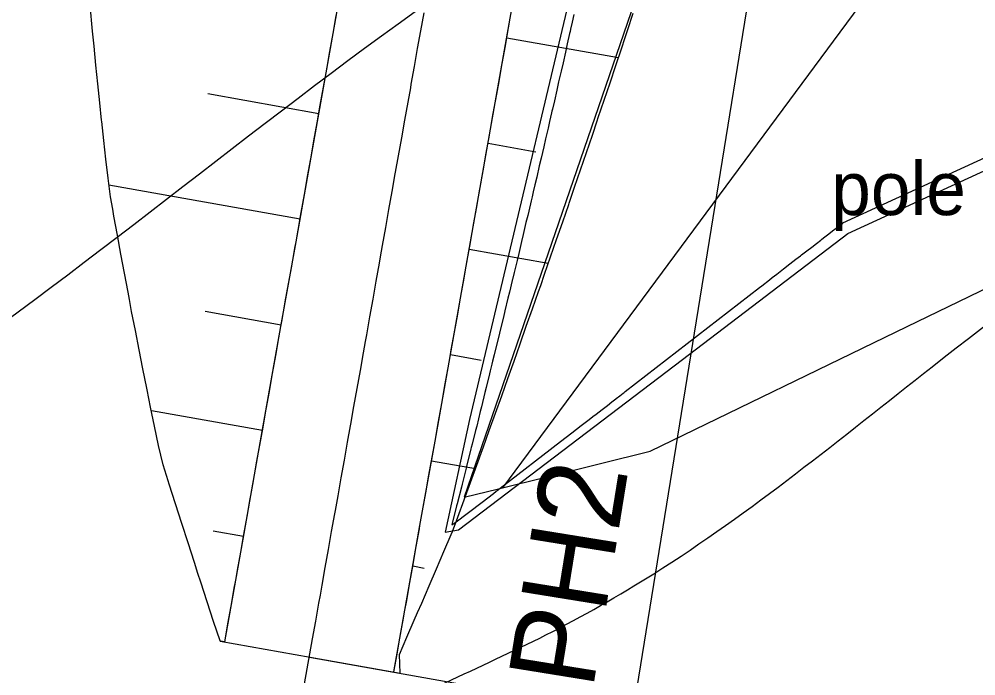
# Model space of a CAD drawing. Extents: x -564037 to -563827, y -1163561 to -1163412.
# Drawn here: x -563935.58 to -563924.45, y -1163502.82 to -1163495.18 of the extents above; entities that cross this region are included whole.
import ezdxf

# ---------------------------------------------------------------- set-up
doc = ezdxf.new("R2010")
doc.units = 0
for name, color, linetype in [('_popis staničení PH2', 7, 'Continuous'), ('_popis staničení T2', 7, 'Continuous'), ('Default', 7, 'Continuous'), ('Line', 7, 'Continuous'), ('Vrstva 24', 7, 'Continuous'), ('Vrstva 26', 7, 'Continuous'), ('Vrstva 40', 7, 'Continuous')]:
    doc.layers.add(name, color=color, linetype=linetype)

msp = doc.modelspace()

# ---------------------------------------------------------------- linework, layer by layer
msp.add_line((-563930.546, -1163501.066), (-563930.51, -1163501.042))
msp.add_lwpolyline([(-563930.469, -1163501.126), (-563927.863, -1163499.14), (-563925.937, -1163497.674), (-563921.059, -1163495.43), (-563912.613, -1163489.681), (-563911.421, -1163482.517), (-563913.266, -1163479.715), (-563914.137, -1163478.749), (-563916.309, -1163476.467), (-563917.281, -1163475.995), (-563923.761, -1163471.506), (-563924, -1163472.797), (-563925.435, -1163477.844), (-563927.008, -1163483.992), (-563927.659, -1163487.507), (-563928.13, -1163490.05), (-563928.806, -1163493.379), (-563930.34, -1163499.841), (-563930.622, -1163501.15)], close=True)
for points in [[(-563931.22, -1163502.778), (-563931.092, -1163502.06), (-563931.007, -1163501.582), (-563930.917, -1163501.075), (-563930.741, -1163500.09), (-563930.566, -1163499.106), (-563930.391, -1163498.121), (-563930.216, -1163497.137), (-563930.041, -1163496.152), (-563929.866, -1163495.168), (-563929.69, -1163494.183), (-563929.515, -1163493.199), (-563929.435, -1163492.745), (-563929.34, -1163492.214), (-563929.165, -1163491.23), (-563928.99, -1163490.245), (-563928.815, -1163489.261), (-563928.639, -1163488.276), (-563928.54, -1163487.717), (-563928.464, -1163487.297)], [(-563933.189, -1163502.428), (-563933.061, -1163501.709), (-563932.976, -1163501.232), (-563932.886, -1163500.725), (-563932.71, -1163499.74), (-563932.535, -1163498.756), (-563932.36, -1163497.771), (-563932.185, -1163496.786), (-563932.01, -1163495.802), (-563931.835, -1163494.817), (-563931.659, -1163493.833), (-563931.484, -1163492.848), (-563931.404, -1163492.395), (-563931.309, -1163491.864), (-563931.134, -1163490.879), (-563930.959, -1163489.895), (-563930.784, -1163488.91), (-563930.608, -1163487.926), (-563930.509, -1163487.367)], [(-563933.243, -1163502.42), (-563933.244, -1163502.418), (-563933.319, -1163502.19), (-563933.395, -1163501.962), (-563933.469, -1163501.733), (-563933.503, -1163501.631), (-563933.543, -1163501.505), (-563933.617, -1163501.277), (-563933.69, -1163501.049), (-563933.762, -1163500.822), (-563933.835, -1163500.594), (-563933.847, -1163500.554), (-563933.906, -1163500.366), (-563933.962, -1163500.141), (-563934.008, -1163499.918), (-563934.053, -1163499.695), (-563934.094, -1163499.494), (-563934.098, -1163499.473), (-563934.142, -1163499.25), (-563934.186, -1163499.027), (-563934.23, -1163498.804), (-563934.273, -1163498.582), (-563934.299, -1163498.442), (-563934.315, -1163498.359), (-563934.357, -1163498.137), (-563934.398, -1163497.915), (-563934.439, -1163497.693), (-563934.479, -1163497.471), (-563934.494, -1163497.391), (-563934.519, -1163497.249), (-563934.548, -1163497.029), (-563934.573, -1163496.809), (-563934.597, -1163496.59), (-563934.621, -1163496.371), (-563934.623, -1163496.353), (-563934.644, -1163496.152), (-563934.666, -1163495.933), (-563934.689, -1163495.714), (-563934.71, -1163495.495), (-563934.727, -1163495.318), (-563934.731, -1163495.277), (-563934.752, -1163495.058)], [(-563932.777, -1163505.821), (-563932.167, -1163502.395), (-563932.13, -1163502.186), (-563932.093, -1163501.978), (-563932.076, -1163501.884), (-563932.056, -1163501.77), (-563932.019, -1163501.562), (-563931.982, -1163501.353), (-563931.945, -1163501.145), (-563931.908, -1163500.937), (-563931.901, -1163500.9), (-563931.871, -1163500.728), (-563931.834, -1163500.52), (-563931.796, -1163500.312), (-563931.759, -1163500.103), (-563931.726, -1163499.915), (-563931.722, -1163499.895), (-563931.685, -1163499.687), (-563931.648, -1163499.479), (-563931.611, -1163499.27), (-563931.574, -1163499.062), (-563931.551, -1163498.931), (-563931.537, -1163498.854), (-563931.5, -1163498.645), (-563931.463, -1163498.437), (-563931.426, -1163498.229), (-563931.389, -1163498.02), (-563931.376, -1163497.946), (-563931.352, -1163497.812), (-563931.315, -1163497.604), (-563931.278, -1163497.396), (-563931.241, -1163497.187), (-563931.204, -1163496.979), (-563931.2, -1163496.962), (-563931.166, -1163496.771), (-563931.129, -1163496.562), (-563931.092, -1163496.354), (-563931.055, -1163496.146), (-563931.025, -1163495.977), (-563931.018, -1163495.937), (-563930.981, -1163495.729), (-563930.944, -1163495.521), (-563930.907, -1163495.313), (-563930.87, -1163495.104)], [(-563931.156, -1163502.575), (-563931.07, -1163502.375), (-563930.983, -1163502.176), (-563930.945, -1163502.086), (-563930.897, -1163501.976), (-563930.811, -1163501.776), (-563930.726, -1163501.577), (-563930.64, -1163501.377), (-563930.555, -1163501.177), (-563930.54, -1163501.142), (-563930.476, -1163500.976), (-563930.403, -1163500.775), (-563930.329, -1163500.573), (-563930.256, -1163500.371), (-563930.19, -1163500.188), (-563930.183, -1163500.169), (-563930.111, -1163499.967), (-563930.038, -1163499.765), (-563929.966, -1163499.563), (-563929.894, -1163499.361), (-563929.849, -1163499.234), (-563929.822, -1163499.159), (-563929.751, -1163498.957), (-563929.679, -1163498.754), (-563929.608, -1163498.552), (-563929.537, -1163498.35), (-563929.512, -1163498.278), (-563929.467, -1163498.148), (-563929.396, -1163497.945), (-563929.326, -1163497.743), (-563929.256, -1163497.54), (-563929.186, -1163497.338), (-563929.181, -1163497.321), (-563929.117, -1163497.135), (-563929.048, -1163496.933), (-563928.978, -1163496.73), (-563928.91, -1163496.528), (-563928.854, -1163496.363), (-563928.841, -1163496.325), (-563928.773, -1163496.122), (-563928.704, -1163495.919), (-563928.637, -1163495.717), (-563928.569, -1163495.514), (-563928.533, -1163495.405), (-563928.501, -1163495.311), (-563928.434, -1163495.108)], [(-563931.156, -1163502.575), (-563931.07, -1163502.375), (-563930.983, -1163502.176), (-563930.945, -1163502.086), (-563930.897, -1163501.976), (-563930.811, -1163501.776), (-563930.726, -1163501.577), (-563930.64, -1163501.377), (-563930.555, -1163501.177), (-563930.54, -1163501.142), (-563930.476, -1163500.976), (-563930.403, -1163500.775), (-563930.329, -1163500.573), (-563930.256, -1163500.371), (-563930.19, -1163500.188), (-563930.183, -1163500.169), (-563930.111, -1163499.967), (-563930.038, -1163499.765), (-563929.966, -1163499.563), (-563929.894, -1163499.361), (-563929.849, -1163499.234), (-563929.822, -1163499.159), (-563929.751, -1163498.957), (-563929.679, -1163498.754), (-563929.608, -1163498.552), (-563929.537, -1163498.35), (-563929.512, -1163498.278), (-563929.467, -1163498.148), (-563929.396, -1163497.945), (-563929.326, -1163497.743), (-563929.256, -1163497.54), (-563929.186, -1163497.338), (-563929.181, -1163497.321), (-563929.117, -1163497.135), (-563929.048, -1163496.933), (-563928.978, -1163496.73), (-563928.91, -1163496.528), (-563928.854, -1163496.363), (-563928.841, -1163496.325), (-563928.773, -1163496.122), (-563928.704, -1163495.919), (-563928.637, -1163495.717), (-563928.569, -1163495.514), (-563928.533, -1163495.405), (-563928.501, -1163495.311), (-563928.434, -1163495.108)], [(-563933.189, -1163502.43), (-563933.189, -1163502.428), (-563933.152, -1163502.22), (-563933.115, -1163502.011), (-563933.078, -1163501.803), (-563933.061, -1163501.709), (-563933.04, -1163501.595), (-563933.003, -1163501.386), (-563932.966, -1163501.178), (-563932.929, -1163500.97), (-563932.892, -1163500.762), (-563932.886, -1163500.725), (-563932.855, -1163500.553), (-563932.818, -1163500.345), (-563932.781, -1163500.137), (-563932.744, -1163499.928), (-563932.71, -1163499.74), (-563932.707, -1163499.72), (-563932.67, -1163499.512), (-563932.633, -1163499.303), (-563932.596, -1163499.095), (-563932.559, -1163498.887), (-563932.535, -1163498.756), (-563932.522, -1163498.679), (-563932.485, -1163498.47), (-563932.447, -1163498.262), (-563932.41, -1163498.054), (-563932.373, -1163497.845), (-563932.36, -1163497.771), (-563932.336, -1163497.637), (-563932.299, -1163497.429), (-563932.262, -1163497.22), (-563932.225, -1163497.012), (-563932.188, -1163496.804), (-563932.185, -1163496.786), (-563932.151, -1163496.596), (-563932.114, -1163496.387), (-563932.077, -1163496.179), (-563932.04, -1163495.971), (-563932.01, -1163495.802), (-563932.003, -1163495.762), (-563931.966, -1163495.554), (-563931.929, -1163495.346), (-563931.892, -1163495.137)], [(-563933.189, -1163502.43), (-563933.189, -1163502.428), (-563933.152, -1163502.22), (-563933.115, -1163502.011), (-563933.078, -1163501.803), (-563933.061, -1163501.709), (-563933.04, -1163501.595), (-563933.003, -1163501.386), (-563932.966, -1163501.178), (-563932.929, -1163500.97), (-563932.892, -1163500.762), (-563932.886, -1163500.725), (-563932.855, -1163500.553), (-563932.818, -1163500.345), (-563932.781, -1163500.137), (-563932.744, -1163499.928), (-563932.71, -1163499.74), (-563932.707, -1163499.72), (-563932.67, -1163499.512), (-563932.633, -1163499.303), (-563932.596, -1163499.095), (-563932.559, -1163498.887), (-563932.535, -1163498.756), (-563932.522, -1163498.679), (-563932.485, -1163498.47), (-563932.447, -1163498.262), (-563932.41, -1163498.054), (-563932.373, -1163497.845), (-563932.36, -1163497.771), (-563932.336, -1163497.637), (-563932.299, -1163497.429), (-563932.262, -1163497.22), (-563932.225, -1163497.012), (-563932.188, -1163496.804), (-563932.185, -1163496.786), (-563932.151, -1163496.596), (-563932.114, -1163496.387), (-563932.077, -1163496.179), (-563932.04, -1163495.971), (-563932.01, -1163495.802), (-563932.003, -1163495.762), (-563931.966, -1163495.554), (-563931.929, -1163495.346), (-563931.892, -1163495.137)], [(-563931.22, -1163502.78), (-563931.22, -1163502.778), (-563931.183, -1163502.57), (-563931.146, -1163502.362), (-563931.108, -1163502.153), (-563931.092, -1163502.06), (-563931.071, -1163501.945), (-563931.034, -1163501.737), (-563930.997, -1163501.528), (-563930.96, -1163501.32), (-563930.923, -1163501.112), (-563930.917, -1163501.075), (-563930.886, -1163500.904), (-563930.849, -1163500.695), (-563930.812, -1163500.487), (-563930.775, -1163500.279), (-563930.741, -1163500.09), (-563930.738, -1163500.07), (-563930.701, -1163499.862), (-563930.664, -1163499.654), (-563930.627, -1163499.445), (-563930.59, -1163499.237), (-563930.566, -1163499.106), (-563930.553, -1163499.029), (-563930.515, -1163498.821), (-563930.478, -1163498.612), (-563930.441, -1163498.404), (-563930.404, -1163498.196), (-563930.391, -1163498.121), (-563930.367, -1163497.987), (-563930.33, -1163497.779), (-563930.293, -1163497.571), (-563930.256, -1163497.362), (-563930.219, -1163497.154), (-563930.216, -1163497.137), (-563930.182, -1163496.946), (-563930.145, -1163496.738), (-563930.108, -1163496.529), (-563930.071, -1163496.321), (-563930.041, -1163496.152), (-563930.034, -1163496.113), (-563929.997, -1163495.904), (-563929.96, -1163495.696), (-563929.922, -1163495.488), (-563929.885, -1163495.279), (-563929.866, -1163495.168)], [(-563931.22, -1163502.78), (-563931.22, -1163502.778), (-563931.183, -1163502.57), (-563931.146, -1163502.362), (-563931.108, -1163502.153), (-563931.092, -1163502.06), (-563931.071, -1163501.945), (-563931.034, -1163501.737), (-563930.997, -1163501.528), (-563930.96, -1163501.32), (-563930.923, -1163501.112), (-563930.917, -1163501.075), (-563930.886, -1163500.904), (-563930.849, -1163500.695), (-563930.812, -1163500.487), (-563930.775, -1163500.279), (-563930.741, -1163500.09), (-563930.738, -1163500.07), (-563930.701, -1163499.862), (-563930.664, -1163499.654), (-563930.627, -1163499.445), (-563930.59, -1163499.237), (-563930.566, -1163499.106), (-563930.553, -1163499.029), (-563930.515, -1163498.821), (-563930.478, -1163498.612), (-563930.441, -1163498.404), (-563930.404, -1163498.196), (-563930.391, -1163498.121), (-563930.367, -1163497.987), (-563930.33, -1163497.779), (-563930.293, -1163497.571), (-563930.256, -1163497.362), (-563930.219, -1163497.154), (-563930.216, -1163497.137), (-563930.182, -1163496.946), (-563930.145, -1163496.738), (-563930.108, -1163496.529), (-563930.071, -1163496.321), (-563930.041, -1163496.152), (-563930.034, -1163496.113), (-563929.997, -1163495.904), (-563929.96, -1163495.696), (-563929.922, -1163495.488), (-563929.885, -1163495.279), (-563929.866, -1163495.168)], [(-563929.126, -1163495.123), (-563929.147, -1163495.215), (-563929.164, -1163495.294), (-563929.17, -1163495.321), (-563929.175, -1163495.344), (-563929.202, -1163495.465), (-563929.225, -1163495.565), (-563929.252, -1163495.687), (-563929.275, -1163495.785), (-563929.303, -1163495.908), (-563929.325, -1163496.006), (-563929.353, -1163496.13), (-563929.375, -1163496.226), (-563929.381, -1163496.251), (-563929.385, -1163496.271), (-563929.409, -1163496.371), (-563929.426, -1163496.447), (-563929.455, -1163496.574), (-563929.477, -1163496.667), (-563929.507, -1163496.796), (-563929.528, -1163496.887), (-563929.558, -1163497.018), (-563929.579, -1163497.107), (-563929.599, -1163497.191), (-563929.612, -1163497.246), (-563929.623, -1163497.295), (-563929.631, -1163497.328), (-563929.663, -1163497.463), (-563929.683, -1163497.548), (-563929.715, -1163497.685), (-563929.735, -1163497.768), (-563929.768, -1163497.907), (-563929.787, -1163497.988), (-563929.821, -1163498.129), (-563929.84, -1163498.208), (-563929.842, -1163498.216), (-563929.843, -1163498.221), (-563929.875, -1163498.356), (-563929.893, -1163498.428), (-563929.928, -1163498.575), (-563929.946, -1163498.648), (-563929.982, -1163498.798), (-563929.999, -1163498.868), (-563930.036, -1163499.021), (-563930.053, -1163499.088), (-563930.071, -1163499.162), (-563930.079, -1163499.194), (-563930.099, -1163499.275), (-563930.107, -1163499.308), (-563930.146, -1163499.468), (-563930.161, -1163499.527), (-563930.201, -1163499.692), (-563930.215, -1163499.747), (-563930.257, -1163499.916), (-563930.27, -1163499.967), (-563930.309, -1163500.125), (-563930.32, -1163500.167), (-563930.324, -1163500.182), (-563930.325, -1163500.186), (-563930.37, -1163500.367), (-563930.38, -1163500.406), (-563930.427, -1163500.593), (-563930.435, -1163500.626), (-563930.485, -1163500.821), (-563930.491, -1163500.845), (-563930.543, -1163501.05), (-563930.547, -1163501.065)], [(-563930.51, -1163501.042), (-563930.194, -1163500.802), (-563930.063, -1163500.701), (-563930.031, -1163500.675), (-563930.02, -1163500.666), (-563929.982, -1163500.641), (-563929.282, -1163500.096), (-563929.151, -1163499.995), (-563929.041, -1163499.91), (-563928.948, -1163499.838), (-563928.905, -1163499.805), (-563928.867, -1163499.777), (-563928.798, -1163499.723), (-563928.736, -1163499.676), (-563928.682, -1163499.634), (-563928.637, -1163499.599), (-563928.634, -1163499.597), (-563928.591, -1163499.564), (-563928.553, -1163499.534), (-563928.54, -1163499.524), (-563928.527, -1163499.513), (-563926.965, -1163498.303), (-563926.939, -1163498.283), (-563926.848, -1163498.212), (-563926.816, -1163498.187), (-563926.763, -1163498.146), (-563926.684, -1163498.085), (-563926.61, -1163498.028), (-563926.541, -1163497.974), (-563926.488, -1163497.934), (-563926.476, -1163497.924), (-563926.415, -1163497.876), (-563926.357, -1163497.832), (-563926.303, -1163497.79), (-563926.252, -1163497.75), (-563926.241, -1163497.741), (-563926.203, -1163497.713), (-563926.157, -1163497.677), (-563926.114, -1163497.643), (-563926.073, -1163497.611), (-563926.047, -1163497.591), (-563926.04, -1163497.586), (-563926.033, -1163497.581), (-563925.996, -1163497.552), (-563925.993, -1163497.549), (-563921.117, -1163495.312)], [(-563930.547, -1163501.065), (-563930.546, -1163501.066)], [(-563933.243, -1163502.42), (-563931.147, -1163502.793), (-563931.148, -1163502.791), (-563931.156, -1163502.575)], [(-563931.147, -1163502.793), (-563931.148, -1163502.791), (-563931.156, -1163502.575)]]:
    msp.add_lwpolyline(points)
at = {"layer": '_popis staničení PH2'}
msp.add_lwpolyline([(-563932.204, -1163502.605), (-563917.436, -1163505.232)], dxfattribs=at)
at = {"layer": '_popis staničení T2'}
msp.add_lwpolyline([(-563928.663, -1163483.434), (-563925.713, -1163486.386), (-563930.105, -1163513.533)], dxfattribs=at)
at = {"layer": 'Default'}
msp.add_lwpolyline([(-563925.948, -1163485.244), (-563926.867, -1163489.1), (-563927.916, -1163493.212), (-563928.032, -1163493.665), (-563928.034, -1163493.674), (-563928.134, -1163494.067), (-563928.211, -1163494.367), (-563929.345, -1163497.668), (-563930.401, -1163500.745), (-563930.002, -1163500.645), (-563928.239, -1163500.208), (-563925.246, -1163498.757), (-563920.654, -1163496.532), (-563920.013, -1163496.222), (-563919.971, -1163496.201), (-563919.419, -1163495.832), (-563914.794, -1163492.742), (-563911.305, -1163489.972), (-563911.26, -1163489.446), (-563911.245, -1163489.265), (-563911.055, -1163487.019)], dxfattribs=at)
at = {"layer": 'Line'}
for p, q in [((-563921.461, -1163489.159), (-563929.957, -1163500.634)), ((-563929.906, -1163495.396), (-563928.607, -1163495.627)), ((-563933.386, -1163496.046), (-563932.094, -1163496.276)), ((-563929.568, -1163496.726), (-563930.125, -1163496.626)), ((-563932.313, -1163497.507), (-563934.537, -1163497.111)), ((-563930.344, -1163497.857), (-563929.423, -1163498.021)), ((-563933.418, -1163498.58), (-563932.532, -1163498.737)), ((-563930.203, -1163499.152), (-563930.563, -1163499.088)), ((-563932.751, -1163499.968), (-563934.044, -1163499.738)), ((-563930.782, -1163500.319), (-563930.27, -1163500.41)), ((-563933.326, -1163501.135), (-563932.97, -1163501.199)), ((-563930.868, -1163501.573), (-563931.001, -1163501.549)), ((-563933.189, -1163502.43), (-563933.243, -1163502.42))]:
    msp.add_line(p, q, dxfattribs=at)
at = {"layer": 'Vrstva 24'}
for points in [[(-563939.075, -1163507.623), (-563938.225, -1163507.164), (-563937.324, -1163506.641), (-563936.436, -1163506.097), (-563935.549, -1163505.552), (-563934.649, -1163505.03), (-563930.625, -1163502.906), (-563929.451, -1163502.347), (-563928.196, -1163501.635), (-563924.955, -1163499.225), (-563920.602, -1163495.57), (-563920.316, -1163495.267), (-563915.394, -1163488.268), (-563914.823, -1163487.183), (-563914.579, -1163485.87), (-563914.81, -1163484.102), (-563915.208, -1163482.646), (-563915.847, -1163480.252), (-563916.025, -1163479.9), (-563916.675, -1163479.113), (-563917.077, -1163478.648)], [(-563942.475, -1163518.079), (-563940.112, -1163517.387), (-563935.904, -1163515.974), (-563933.959, -1163515.268), (-563929.245, -1163513.665), (-563925.032, -1163512.173), (-563922.819, -1163511.166), (-563919.003, -1163509.075), (-563915.156, -1163506.928), (-563914.035, -1163506.214), (-563913.139, -1163505.478), (-563911.421, -1163503.905), (-563910.565, -1163503.115), (-563909.689, -1163502.349), (-563908.668, -1163501.532), (-563907.622, -1163500.746), (-563906.572, -1163499.965), (-563905.922, -1163499.466)]]:
    msp.add_spline(points, degree=3, dxfattribs=at)
at = {"layer": 'Vrstva 26'}
for points in [[(-563938.486, -1163500.528), (-563938.463, -1163500.513), (-563937.665, -1163500.022), (-563936.97, -1163499.566), (-563930.777, -1163494.949), (-563928.884, -1163493.45), (-563928.656, -1163493.192), (-563928.195, -1163492.447), (-563924.372, -1163485.735), (-563923.788, -1163484.5), (-563923.604, -1163483.639), (-563923.611, -1163481.604), (-563923.712, -1163481.017), (-563924.518, -1163478.475), (-563924.689, -1163477.919), (-563924.751, -1163477.798), (-563925.518, -1163476.583), (-563926.306, -1163475.384), (-563927.092, -1163474.184), (-563927.851, -1163472.968), (-563928.532, -1163471.813), (-563929.192, -1163470.645), (-563929.849, -1163469.476), (-563930.525, -1163468.317), (-563930.688, -1163468.07), (-563931.156, -1163467.471), (-563931.276, -1163467.321)], [(-563940.525, -1163513.198), (-563938.9, -1163512.504), (-563932.611, -1163509.84), (-563931.885, -1163509.567), (-563930.901, -1163509.188), (-563926.659, -1163507.216), (-563923.334, -1163505.549), (-563921.652, -1163504.643), (-563920.105, -1163503.651), (-563917.012, -1163501.201), (-563913.048, -1163497.944), (-563912.649, -1163497.606), (-563912.385, -1163497.353), (-563911.289, -1163496.159), (-563908.991, -1163493.383), (-563906.775, -1163490.536), (-563906.699, -1163490.433)]]:
    msp.add_spline(points, degree=3, dxfattribs=at)

# ---------------------------------------------------------------- texts
at = {"layer": '_popis staničení T2'}
msp.add_text('0+011 30 Hrázka PH2', height=1, rotation=80.811, dxfattribs=at).set_placement((-563930.598, -1163513.453))
at = {"layer": 'Vrstva 40'}
msp.add_text('pole', height=0.62, dxfattribs=at).set_placement((-563926.13, -1163497.46))

doc.saveas('drawing.dxf')
